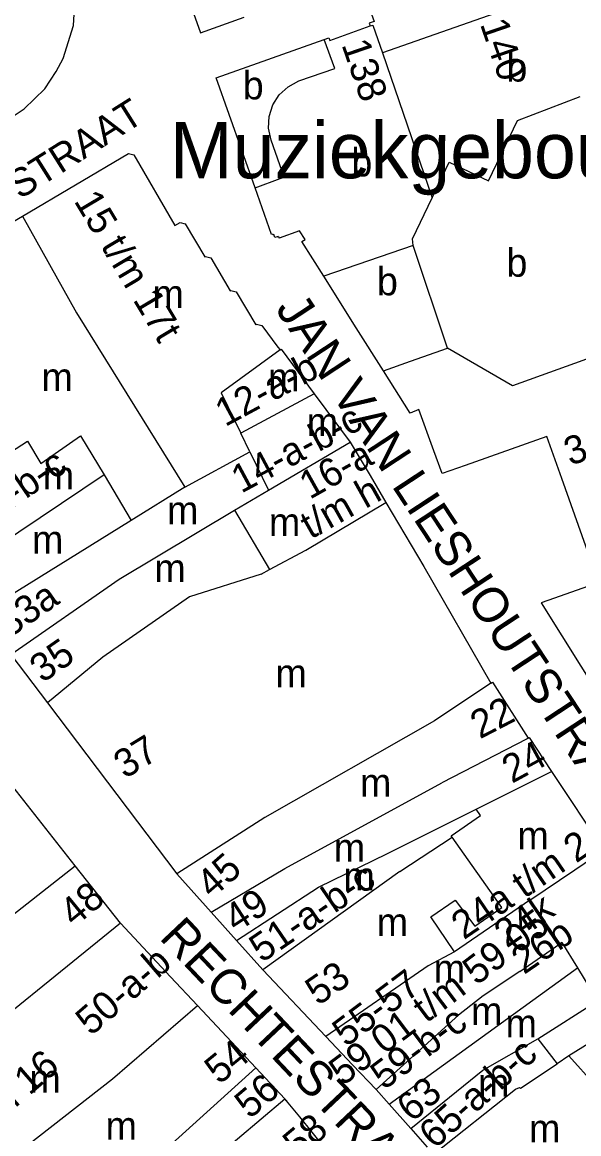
# Model space of a CAD drawing. Extents: x 160673 to 161924, y 382258 to 384145.
# Drawn here: x 161359.3 to 161438.3, y 383169.3 to 383327.4 of the extents above; entities that cross this region are included whole.
import ezdxf

# ---------------------------------------------------------------- set-up
doc = ezdxf.new("R2010")
doc.units = 0
for name, color, linetype in [('BLT_Basislijn', 7, 'Continuous'), ('BLT_Bebouwing', 7, 'Continuous'), ('BLT_Bebouwing_beschrifting', 7, 'Continuous'), ('BLT_Centroide', 7, 'Continuous'), ('BLT_Huisnummer', 7, 'Continuous'), ('BLT_Huisnummer_reeks', 7, 'Continuous'), ('BLT_Onderdoorgang_en_onderverdeling', 7, 'Continuous'), ('BLT_Onderverdeling_panden', 7, 'Continuous'), ('BLT_Straatnaam', 7, 'Continuous'), ('BLT_Straatnaam_verkleind', 7, 'Continuous')]:
    doc.layers.add(name, color=color, linetype=linetype)

msp = doc.modelspace()

# ---------------------------------------------------------------- linework, layer by layer
at = {"layer": 'BLT_Basislijn'}
msp.add_lwpolyline([(161354.32, 383311.3), (161355.34, 383312.31), (161359.55, 383315.09), (161362.49, 383317.94), (161364.1, 383320.41), (161365.06, 383322.25), (161366.56, 383326.94), (161366.85, 383332.59), (161366.55, 383335.51), (161366, 383339.32), (161364.95, 383343.45), (161344.75, 383399.92)], dxfattribs=at)
at = {"layer": 'BLT_Bebouwing'}
for p, q in [((161350.35, 383294.53), (161359.27, 383299.83)), ((161400.75, 383274.56), (161405.85, 383267.67)), ((161408.68, 383262.91), (161410.93, 383259.1)), ((161410.93, 383259.1), (161416.34, 383250)), ((161416.34, 383250), (161425.86, 383233.38)), ((161362.84, 383230.58), (161381.24, 383206.27)), ((161366.8, 383207.39), (161357.38, 383219.36)), ((161386.1, 383200.83), (161389.71, 383196.79)), ((161380.34, 383191.63), (161373.21, 383199.25)), ((161393.43, 383192.62), (161402.41, 383183.11)), ((161380.34, 383191.63), (161384.18, 383187.52)), ((161384.18, 383187.52), (161392.44, 383178.67)), ((161402.41, 383183.11), (161406.19, 383179.11)), ((161392.44, 383178.67), (161396.55, 383174.27)), ((161406.19, 383179.11), (161409.54, 383175.57)), ((161398.68, 383171.7), (161396.55, 383174.27)), ((161396.74, 383174.07), (161396.84, 383173.96)), ((161411.39, 383173.51), (161414.47, 383170.05)), ((161402.23, 383167.35), (161398.68, 383171.7)), ((161414.47, 383170.05), (161416.78, 383167.37))]:
    msp.add_line(p, q, dxfattribs=at)
for points in [[(161382.39, 383332.07), (161384.59, 383325.89), (161390.81, 383328.1)], [(161407.28, 383333), (161409.25, 383327.48), (161408.55, 383327.24), (161408.68, 383326.86)], [(161402.18, 383324.95), (161402.81, 383325.18), (161402.95, 383324.79), (161408.68, 383326.86)], [(161392.34, 383303.84), (161386.8, 383319.47), (161402.18, 383324.95)], [(161359.27, 383299.83), (161374.34, 383308.72), (161375.11, 383308.54), (161380.96, 383298.5), (161381.68, 383298.92), (161382.42, 383298.72), (161385.18, 383294.04), (161385.31, 383294.08), (161386.04, 383293.89), (161388.8, 383289.21), (161388.92, 383289.26), (161389.65, 383289.07), (161392.43, 383284.37), (161392.55, 383284.43), (161393.3, 383284.24), (161395.58, 383281.16), (161395.93, 383280.81)], [(161402.1, 383291.27), (161399.01, 383296.19), (161399.46, 383296.47), (161398.67, 383297.71), (161395.79, 383296.7), (161395.75, 383296.81), (161395.66, 383296.78), (161395.61, 383296.93), (161395.16, 383296.77), (161395, 383297.21), (161394.81, 383297.14), (161394.79, 383297.26), (161394.7, 383297.22), (161392.34, 383303.84)], [(161410.57, 383277.81), (161406.73, 383283.92), (161402.1, 383291.27)], [(161395.93, 383280.81), (161396.06, 383280.89), (161400.75, 383274.56)], [(161440.66, 383249.13), (161435.92, 383262.48), (161433.78, 383268.46), (161422.18, 383264.37), (161418.91, 383263.22), (161417.75, 383266.43), (161415.63, 383272.29), (161414.36, 383271.79), (161410.57, 383277.81)], [(161405.85, 383267.67), (161408.68, 383262.91)], [(161440.66, 383249.13), (161441.17, 383247.71), (161434.9, 383245.47), (161432.99, 383244.79), (161441.57, 383231.12)], [(161357.63, 383237.45), (161362.84, 383230.58)], [(161425.86, 383233.38), (161426.09, 383233.53), (161431.16, 383225.58)], [(161431.16, 383225.58), (161431.29, 383225.65), (161434.47, 383220.8)], [(161434.47, 383220.8), (161441.92, 383209.63)], [(161373.21, 383199.25), (161366.8, 383207.39)], [(161381.24, 383206.27), (161386.1, 383200.83)], [(161389.71, 383196.79), (161393.43, 383192.62)], [(161409.54, 383175.57), (161411.39, 383173.51)]]:
    msp.add_lwpolyline(points, dxfattribs=at)
at = {"layer": 'BLT_Onderdoorgang_en_onderverdeling'}
msp.add_lwpolyline([(161392.34, 383303.84), (161395.92, 383305.16), (161396.49, 383305.37), (161394.62, 383310.63), (161394.25, 383312.32), (161394.34, 383314.01), (161394.89, 383315.65), (161395.77, 383317.09), (161397.05, 383318.22), (161398.56, 383319.04), (161403.67, 383320.82), (161402.18, 383324.95)], dxfattribs=at)
at = {"layer": 'BLT_Onderverdeling_panden'}
for p, q in [((161440.02, 383333.44), (161410.43, 383323.03)), ((161410.43, 383323.03), (161417.52, 383302.42)), ((161359.27, 383299.83), (161366.95, 383286.08)), ((161414.8, 383295.66), (161402.1, 383291.27)), ((161419.68, 383281.03), (161414.8, 383295.66)), ((161366.95, 383286.08), (161382.35, 383261.26)), ((161400.75, 383274.56), (161390.31, 383268.95)), ((161391.59, 383266.29), (161394.23, 383260.83)), ((161370.9, 383263.04), (161349.5, 383248.64)), ((161370.9, 383263.04), (161374.73, 383256.53)), ((161382.35, 383261.26), (161374.73, 383256.53)), ((161389.41, 383257.99), (161394.23, 383260.83)), ((161389.41, 383257.99), (161394.41, 383249.55)), ((161374.73, 383256.53), (161353.39, 383243.28)), ((161393.21, 383248.91), (161394.41, 383249.55)), ((161425.86, 383233.38), (161417.82, 383228.01)), ((161423.78, 383215.46), (161434.47, 383220.8)), ((161411.15, 383209.15), (161423.78, 383215.46)), ((161412.9, 383206.59), (161420.37, 383211.47)), ((161401.35, 383204.39), (161411.15, 383209.15)), ((161412.9, 383206.59), (161393.43, 383192.62)), ((161389.71, 383196.79), (161401.35, 383204.39)), ((161431.39, 383202.5), (161420.7, 383195.18)), ((161432.65, 383200.66), (161431.39, 383202.5)), ((161432.65, 383200.66), (161433.78, 383199.03)), ((161420.7, 383195.18), (161417.32, 383200.13)), ((161433.78, 383199.03), (161435.66, 383196.32)), ((161429.98, 383192.36), (161435.66, 383196.32)), ((161435.94, 383196.51), (161435.66, 383196.32)), ((161435.94, 383196.51), (161438.16, 383192.89)), ((161411.39, 383173.51), (161438.16, 383192.89)), ((161438.16, 383192.89), (161441.02, 383188.2)), ((161429.98, 383192.36), (161424.77, 383188.92)), ((161453.36, 383190.71), (161436.92, 383180.36)), ((161424.69, 383178.33), (161432.52, 383182.79)), ((161432.52, 383182.79), (161435.25, 383179.25)), ((161436.92, 383180.36), (161435.25, 383179.25)), ((161436.92, 383180.36), (161440.65, 383176.19)), ((161379.54, 383166.97), (161392.44, 383178.67)), ((161414.47, 383170.05), (161424.69, 383178.33)), ((161417.66, 383166.35), (161429.37, 383175.66)), ((161382.95, 383162.79), (161396.55, 383174.27))]:
    msp.add_line(p, q, dxfattribs=at)
for points in [[(161408.68, 383326.86), (161409.06, 383327), (161410.43, 383323.03)], [(161417.52, 383302.42), (161419.94, 383307.49), (161425.52, 383304.83), (161429.63, 383313.44), (161438.52, 383316.81)], [(161414.8, 383295.66), (161414.73, 383296.58), (161417.52, 383302.42)], [(161395.93, 383280.81), (161387.54, 383274.68), (161390.31, 383268.95)], [(161410.57, 383277.81), (161414.44, 383279.21), (161419.68, 383281.03)], [(161448.9, 383274.8), (161447.64, 383278.01), (161441.8, 383280.32), (161428.94, 383275.69), (161419.68, 383281.03)], [(161343.69, 383257.28), (161359.99, 383267.81), (161361.92, 383264.62), (161367.53, 383268.57), (161370.9, 383263.04)], [(161391.59, 383266.29), (161390.31, 383268.95)], [(161394.23, 383260.83), (161405.85, 383267.67)], [(161382.35, 383261.26), (161391.59, 383266.29)], [(161394.41, 383249.55), (161399.54, 383252.29), (161410.93, 383259.1)], [(161357.63, 383237.45), (161373.03, 383248.17), (161389.41, 383257.99)], [(161393.21, 383248.91), (161383.03, 383245.67)], [(161383.03, 383245.67), (161370.73, 383237.1), (161362.84, 383230.58)], [(161417.82, 383228.01), (161393.74, 383214.3), (161381.24, 383206.27)], [(161431.16, 383225.58), (161431, 383225.49), (161418.86, 383219.2)], [(161386.1, 383200.83), (161396.55, 383207.04), (161418.86, 383219.2)], [(161420.37, 383211.47), (161420.23, 383211.67), (161424.38, 383214.55), (161423.78, 383215.46)], [(161417.32, 383200.13), (161420.79, 383202.5), (161423.57, 383198.83), (161427.43, 383201.47), (161420.37, 383211.47)], [(161431.39, 383202.5), (161437.76, 383206.85), (161441.92, 383209.63)], [(161320.71, 383193.3), (161331.53, 383179.7), (161366.8, 383207.39)], [(161373.21, 383199.25), (161347.85, 383178.66), (161352.86, 383172.98)], [(161420.7, 383195.18), (161416.92, 383193.16), (161402.41, 383183.11)], [(161424.77, 383188.92), (161421.26, 383186.16), (161409.54, 383175.57)], [(161432.52, 383182.79), (161441.02, 383188.2)], [(161355.17, 383170.11), (161358.25, 383166.29), (161372.09, 383177.09), (161384.18, 383187.52)], [(161429.37, 383175.66), (161429.94, 383175.89), (161430.05, 383175.76), (161435.25, 383179.25)]]:
    msp.add_lwpolyline(points, dxfattribs=at)

# ---------------------------------------------------------------- texts
at = {"layer": 'BLT_Bebouwing_beschrifting'}
msp.add_text('Muziekgebouw', height=8, dxfattribs=at).set_placement((161380.24, 383305.2))
at = {"layer": 'BLT_Centroide'}
for s, p in [('b', (161428.06, 383318.96)), ('b', (161390.59, 383316.43)), ('b', (161406.02, 383305.47)), ('b', (161428.06, 383291.21)), ('b', (161409.66, 383288.56)), ('m', (161377.77, 383286.77)), ('m', (161361.99, 383274.93)), ('m', (161394.18, 383274.91)), ('m', (161399.68, 383268.56)), ('m', (161362.18, 383260.94)), ('m', (161379.83, 383256)), ('m', (161394.31, 383254.31)), ('m', (161360.64, 383251.82)), ('m', (161378.03, 383247.76)), ('m', (161395.24, 383232.81)), ('m', (161407.25, 383217.25)), ('m', (161429.62, 383209.73)), ('m', (161403.54, 383208)), ('m', (161404.91, 383203.94)), ('m', (161409.63, 383197.41)), ('m', (161417.73, 383190.81)), ('m', (161423.03, 383184.75)), ('m', (161427.94, 383183.01)), ('m', (161360.27, 383175.16)), ('m', (161424.02, 383174.56)), ('m', (161371.1, 383168.44)), ('m', (161431.27, 383168.06))]:
    msp.add_text(s, height=4, dxfattribs=at).set_placement(p)
at = {"layer": 'BLT_Huisnummer'}
for s, rotation, p in [('33a', 34.8369, (161357.46, 383239.76)), ('22', 27.3727, (161424.29, 383225.38)), ('37', 31.4373, (161373.85, 383219.71)), ('45', 41.2437, (161386.22, 383202.64)), ('48', 39.2752, (161366.65, 383198.6)), ('53', 34.7052, (161401.29, 383187.42)), ('54', 39.288, (161387.25, 383176.19)), ('63', 40.0836, (161414.61, 383170.82))]:
    msp.add_text(s, height=4, rotation=rotation, dxfattribs=at).set_placement(p)
at = {"layer": 'BLT_Huisnummer_reeks'}
for s, rotation, p in [('140', 288.9812, (161424.27, 383327.15)), ('138', 288.9812, (161404.6, 383324.22)), ('15 t/m 17t', 300.8256, (161366.53, 383301.98)), ('12-a-b', 28.2451, (161388.08, 383269.79)), ('14-a-b-c', 28.2451, (161390.37, 383260.32)), ('3-5', 19.5226, (161437.12, 383264.28)), ('16-a', 29.2451, (161400.11, 383259.45)), ('31-a-b-c', 34.4279, (161349.46, 383252.47)), ('t/m h', 29.2451, (161400.24, 383253.79)), ('35', 34.8369, (161362.13, 383233.33)), ('24', 28.5103, (161428.85, 383219.06)), ('24a t/m 24h', 34.3732, (161422.01, 383196.81)), ('51-a-b-c', 34.3626, (161393.3, 383193.53)), ('49', 33.114, (161389.65, 383197.82)), ('24k', 34.3732, (161428.1, 383195.64)), ('59 01 t/m 59 05', 36.9598, (161404.79, 383176)), ('26b', 34.3732, (161430.56, 383191.87)), ('50-a-b', 40.7885, (161369.02, 383183.11)), ('55-57', 36.9421, (161405.27, 383181.52)), ('59-b-c', 36.9598, (161410.68, 383175.43)), ('65-a-b-c', 41.806, (161417.88, 383167)), ('10 t/m 16', 40.7885, (161347.9, 383163.98)), ('56', 40.1849, (161391.58, 383171.29)), ('60-58', 39.9916, (161392.49, 383160.64))]:
    msp.add_text(s, height=4, rotation=rotation, dxfattribs=at).set_placement(p)
at = {"layer": 'BLT_Straatnaam'}
for s, rotation, p in [('JAN VAN LIESHOUTSTRAAT', 303.3195, (161395.14, 383286.62)), ('RECHTESTRAAT', 313.4184, (161378.6, 383197.11))]:
    msp.add_text(s, height=5, rotation=rotation, dxfattribs=at).set_placement(p)
at = {"layer": 'BLT_Straatnaam_verkleind'}
msp.add_text('JAN VAN HOOFFSTRAAT', height=4, rotation=32.1803, dxfattribs=at).set_placement((161322.68, 383279.33))

doc.saveas('drawing.dxf')
